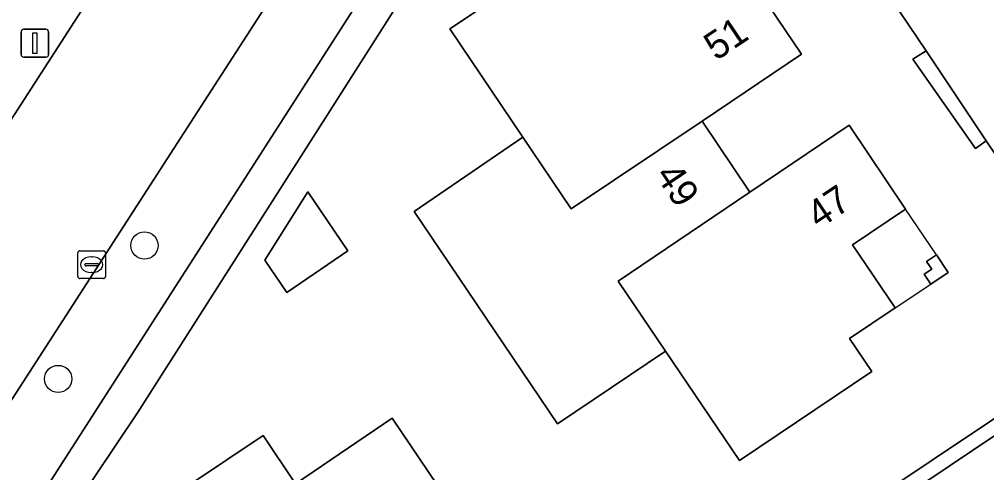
# Model space of a CAD drawing. Extents: x 158793 to 159888, y 384317 to 385256.
# Drawn here: x 158945.21 to 158979.96, y 384710.92 to 384727.22 of the extents above; entities that cross this region are included whole.
import ezdxf

# ---------------------------------------------------------------- set-up
doc = ezdxf.new("R2010")
doc.units = 0
for name, color, linetype in [('IMGEO_Berm_groen', 7, 'Continuous'), ('IMGEO_Boom', 7, 'Continuous'), ('IMGEO_Erf', 7, 'Continuous'), ('IMGEO_Groenvoorziening', 7, 'Continuous'), ('IMGEO_Haag', 7, 'Continuous'), ('IMGEO_Kolk', 7, 'Continuous'), ('IMGEO_Lichtmast', 7, 'Continuous'), ('IMGEO_Pand', 7, 'Continuous'), ('IMGEO_Pand_nummerreeks', 7, 'Continuous'), ('IMGEO_Pand_overbouw', 7, 'Continuous'), ('IMGEO_Parkeervlak_open', 7, 'Continuous'), ('IMGEO_Rijbaan_lokaal_open', 7, 'Continuous')]:
    doc.layers.add(name, color=color, linetype=linetype)

msp = doc.modelspace()

# ---------------------------------------------------------------- linework, layer by layer
at = {"layer": 'IMGEO_Berm_groen'}
for points in [[(158964.561, 384743.963), (158951.852, 384724.265), (158938.197, 384703.116)], [(158942.526, 384699.967), (158952.229, 384685.559), (158953.693, 384686.565), (158953.964, 384686.744), (158953.822, 384686.947), (158952.786, 384686.235), (158941.142, 384702.551), (158965.512, 384740.522)]]:
    msp.add_lwpolyline(points, dxfattribs=at)
msp.add_lwpolyline([(158947.905, 384728.262), (158945.951, 384729.508), (158927.819, 384701.473), (158929.826, 384700.232)], close=True, dxfattribs=at)
at = {"layer": 'IMGEO_Boom'}
for centre in [(158949.703, 384719.09), (158946.602, 384714.293)]:
    msp.add_circle(centre, 0.489, dxfattribs=at)
at = {"layer": 'IMGEO_Erf'}
for points in [[(158971.282, 384728.974), (158973.308, 384725.961), (158969.737, 384723.562), (158971.458, 384721.007), (158975.024, 384723.411), (158977.051, 384720.4), (158975.145, 384719.117), (158976.676, 384716.847), (158975.031, 384715.747), (158975.834, 384714.563), (158971.077, 384711.36), (158968.423, 384715.291), (158964.538, 384712.684), (158959.388, 384720.306), (158963.298, 384722.985), (158960.673, 384726.876), (158965.412, 384730.041), (158966.192, 384728.858), (158967.837, 384729.959), (158969.365, 384727.685)], [(158957.014, 384718.901), (158954.817, 384717.404), (158954.031, 384718.558), (158955.573, 384721.015)], [(158978.159, 384718.754), (158978.583, 384718.123), (158977.952, 384717.701), (158977.713, 384718.058), (158977.986, 384718.241), (158977.802, 384718.514)], [(158961.859, 384708.055), (158960.676, 384707.255), (158962.987, 384703.797), (158960.062, 384701.827), (158959.198, 384703.109), (158957.19, 384701.758), (158955.173, 384700.402), (158956.052, 384699.091), (158953.129, 384697.13), (158947.547, 384705.451), (158949.843, 384706.973), (158948.68, 384708.713), (158951.323, 384710.489), (158953.966, 384712.265), (158955.134, 384710.528), (158958.604, 384712.879)]]:
    msp.add_lwpolyline(points, close=True, dxfattribs=at)
for points in [[(158959.613, 384729.029), (158955.43, 384722.46), (158949.45, 384713.078), (158942.598, 384702.871)], [(158980.664, 384721.786), (158979.947, 384722.856), (158979.559, 384722.571), (158977.312, 384725.783), (158977.782, 384726.084), (158976.839, 384727.49)], [(158971.722, 384707.173), (158984.222, 384715.527)]]:
    msp.add_lwpolyline(points, dxfattribs=at)
at = {"layer": 'IMGEO_Groenvoorziening'}
for points in [[(158965.491, 384739.134), (158966.078, 384738.835), (158966.613, 384739.202), (158965.512, 384740.522), (158941.142, 384702.551), (158952.786, 384686.235), (158953.822, 384686.947), (158950.206, 384692.135), (158952.639, 384693.793), (158952.375, 384694.187), (158951.593, 384693.727), (158949.898, 384692.576), (158948.229, 384695.075), (158942.598, 384702.871), (158949.45, 384713.078), (158955.43, 384722.46), (158959.613, 384729.029), (158959.225, 384729.429)], [(158977.782, 384726.084), (158977.312, 384725.783), (158979.559, 384722.571), (158979.947, 384722.856)], [(158980.664, 384721.786), (158980.257, 384721.539), (158984.222, 384715.527), (158971.722, 384707.173), (158972.017, 384706.723), (158972.264, 384706.889), (158982.666, 384713.882), (158984.939, 384715.41)]]:
    msp.add_lwpolyline(points, close=True, dxfattribs=at)
at = {"layer": 'IMGEO_Haag'}
for points in [[(158965.491, 384739.134), (158966.078, 384738.835), (158966.613, 384739.202), (158965.512, 384740.522), (158941.142, 384702.551), (158952.786, 384686.235), (158953.822, 384686.947), (158950.206, 384692.135), (158952.639, 384693.793), (158952.375, 384694.187), (158951.593, 384693.727), (158949.898, 384692.576), (158948.229, 384695.075), (158942.598, 384702.871), (158949.45, 384713.078), (158955.43, 384722.46), (158959.613, 384729.029), (158959.225, 384729.429)], [(158977.782, 384726.084), (158977.312, 384725.783), (158979.559, 384722.571), (158979.947, 384722.856)], [(158980.664, 384721.786), (158980.257, 384721.539), (158984.222, 384715.527), (158971.722, 384707.173), (158972.017, 384706.723), (158972.264, 384706.889), (158982.666, 384713.882), (158984.939, 384715.41)]]:
    msp.add_lwpolyline(points, close=True, dxfattribs=at)
at = {"layer": 'IMGEO_Kolk'}
for p, q in [((158947.381, 384718.901), (158948.233, 384718.901)), ((158947.306, 384717.975), (158947.306, 384718.827)), ((158947.794, 384718.681), (158947.819, 384718.681)), ((158948.307, 384718.827), (158948.307, 384717.975)), ((158947.565, 384718.395), (158947.565, 384718.407)), ((158948.003, 384718.358), (158947.605, 384718.358)), ((158947.608, 384718.444), (158948.006, 384718.444)), ((158948.049, 384718.407), (158948.049, 384718.395)), ((158948.233, 384717.901), (158947.381, 384717.901)), ((158947.817, 384718.121), (158947.792, 384718.121))]:
    msp.add_line(p, q, dxfattribs=at)
for points in [[(158947.381, 384718.901), (158948.233, 384718.901)], [(158947.306, 384717.975), (158947.306, 384718.827)], [(158948.307, 384718.827), (158948.307, 384717.975)], [(158948.233, 384717.901), (158947.381, 384717.901)]]:
    msp.add_lwpolyline(points, dxfattribs=at)
for centre, radius, start, end in [((158947.383, 384718.825), 0.0765, 91.552, 178.448), ((158947.383, 384718.825), 0.0765, 91.552, 178.448), ((158948.231, 384718.825), 0.0765, 1.552, 88.448), ((158948.231, 384718.825), 0.0765, 1.552, 88.448), ((158947.605, 384718.404), 0.0403, 85.8775, 175.7526), ((158947.602, 384718.394), 0.0366, 178.938, 274.7102), ((158948.006, 384718.401), 0.043, 264.8664, 352.4533), ((158948.01, 384718.406), 0.0386, 1.7309, 96.639), ((158947.383, 384717.977), 0.0765, 181.552, 268.448), ((158947.383, 384717.977), 0.0765, 181.552, 268.448), ((158948.231, 384717.977), 0.0765, 271.552, 358.448), ((158948.231, 384717.977), 0.0765, 271.552, 358.448)]:
    msp.add_arc(centre, radius, start, end, dxfattribs=at)
for centre, major_axis, ratio, start_param, end_param in [((158947.793, 384718.401), (-0.387, 0.002), 0.722429, 4.712389, 7.853982), ((158947.818, 384718.401), (-0.39, 0.002), 0.717154, 1.570796, 4.712389)]:
    msp.add_ellipse(centre, major_axis=major_axis, ratio=ratio, start_param=start_param, end_param=end_param, dxfattribs=at)
at = {"layer": 'IMGEO_Lichtmast'}
for p, q in [((158945.372, 384726.86), (158946.162, 384726.86)), ((158946.162, 384726.86), (158945.372, 384726.86)), ((158945.272, 384725.96), (158945.272, 384726.76)), ((158945.272, 384726.76), (158945.272, 384725.96)), ((158946.262, 384726.76), (158946.262, 384725.96)), ((158946.262, 384725.96), (158946.262, 384726.76)), ((158946.162, 384725.86), (158945.372, 384725.86)), ((158945.372, 384725.86), (158946.162, 384725.86))]:
    msp.add_line(p, q, dxfattribs=at)
msp.add_lwpolyline([(158945.692, 384726.735), (158945.842, 384726.735), (158945.842, 384725.985), (158945.692, 384725.985), (158945.692, 384726.735)], dxfattribs=at)
for centre, start, end in [((158945.372, 384726.76), 90, 180), ((158945.372, 384726.76), 90, 180), ((158946.162, 384726.76), 0, 90), ((158946.162, 384726.76), 360, 90), ((158945.372, 384725.96), 180, 270), ((158945.372, 384725.96), 180, 270), ((158946.162, 384725.96), 270, 0), ((158946.162, 384725.96), 270, 0)]:
    msp.add_arc(centre, 0.1, start, end, dxfattribs=at)
at = {"layer": 'IMGEO_Pand'}
for points in [[(158971.282, 384728.974), (158969.365, 384727.685), (158967.837, 384729.959), (158966.192, 384728.858), (158965.412, 384730.041), (158960.673, 384726.876), (158963.298, 384722.985), (158965.038, 384720.405), (158969.737, 384723.562), (158973.308, 384725.961)], [(158966.72, 384717.813), (158971.458, 384721.007), (158969.737, 384723.562), (158965.038, 384720.405), (158963.298, 384722.985), (158959.388, 384720.306), (158964.538, 384712.684), (158968.423, 384715.291)], [(158975.145, 384719.117), (158977.051, 384720.4), (158975.024, 384723.411), (158971.458, 384721.007), (158966.72, 384717.813), (158968.423, 384715.291), (158971.077, 384711.36), (158975.834, 384714.563), (158975.031, 384715.747), (158976.676, 384716.847)], [(158957.014, 384718.901), (158955.573, 384721.015), (158954.031, 384718.558), (158954.817, 384717.404)], [(158978.159, 384718.754), (158977.802, 384718.514), (158977.986, 384718.241), (158977.713, 384718.058), (158977.952, 384717.701), (158978.583, 384718.123)], [(158961.859, 384708.055), (158958.604, 384712.879), (158955.134, 384710.528), (158953.966, 384712.265), (158951.323, 384710.489), (158957.19, 384701.758), (158959.198, 384703.109), (158960.062, 384701.827), (158962.987, 384703.797), (158960.676, 384707.255)]]:
    msp.add_lwpolyline(points, close=True, dxfattribs=at)
at = {"layer": 'IMGEO_Pand_overbouw'}
msp.add_lwpolyline([(158976.676, 384716.847), (158977.952, 384717.701), (158978.583, 384718.123), (158978.159, 384718.754), (158977.051, 384720.4), (158975.145, 384719.117)], close=True, dxfattribs=at)
at = {"layer": 'IMGEO_Parkeervlak_open'}
msp.add_lwpolyline([(158985.469, 384709.698), (158982.666, 384713.882), (158972.264, 384706.889), (158975.08, 384702.746)], close=True, dxfattribs=at)
at = {"layer": 'IMGEO_Rijbaan_lokaal_open'}
for points in [[(158985.137, 384785.92), (158983.24, 384782.984), (158982.273, 384781.486), (158980.086, 384778.1), (158963.673, 384752.692), (158961.503, 384749.332), (158960.53, 384747.827), (158958.368, 384744.479), (158956.318, 384741.306), (158950.088, 384731.646), (158947.905, 384728.262), (158929.826, 384700.232), (158927.919, 384697.276), (158926.091, 384694.44), (158930.284, 384691.674), (158930.652, 384691.431), (158935.092, 384698.307), (158936.004, 384699.719), (158938.197, 384703.116), (158951.852, 384724.265), (158964.561, 384743.963), (158966.233, 384746.553), (158978.977, 384766.305)], [(158976.839, 384727.49), (158977.782, 384726.084), (158979.947, 384722.856), (158980.664, 384721.786)]]:
    msp.add_lwpolyline(points, dxfattribs=at)

# ---------------------------------------------------------------- texts
at = {"layer": 'IMGEO_Pand_nummerreeks'}
for s, rotation, p in [('51', 33.8905, (158970.244, 384725.709)), ('49', 303.9647, (158968.033, 384721.617)), ('47', 33.9879, (158973.935, 384719.662))]:
    msp.add_text(s, height=1, rotation=rotation, dxfattribs=at).set_placement(p)

doc.saveas('drawing.dxf')
